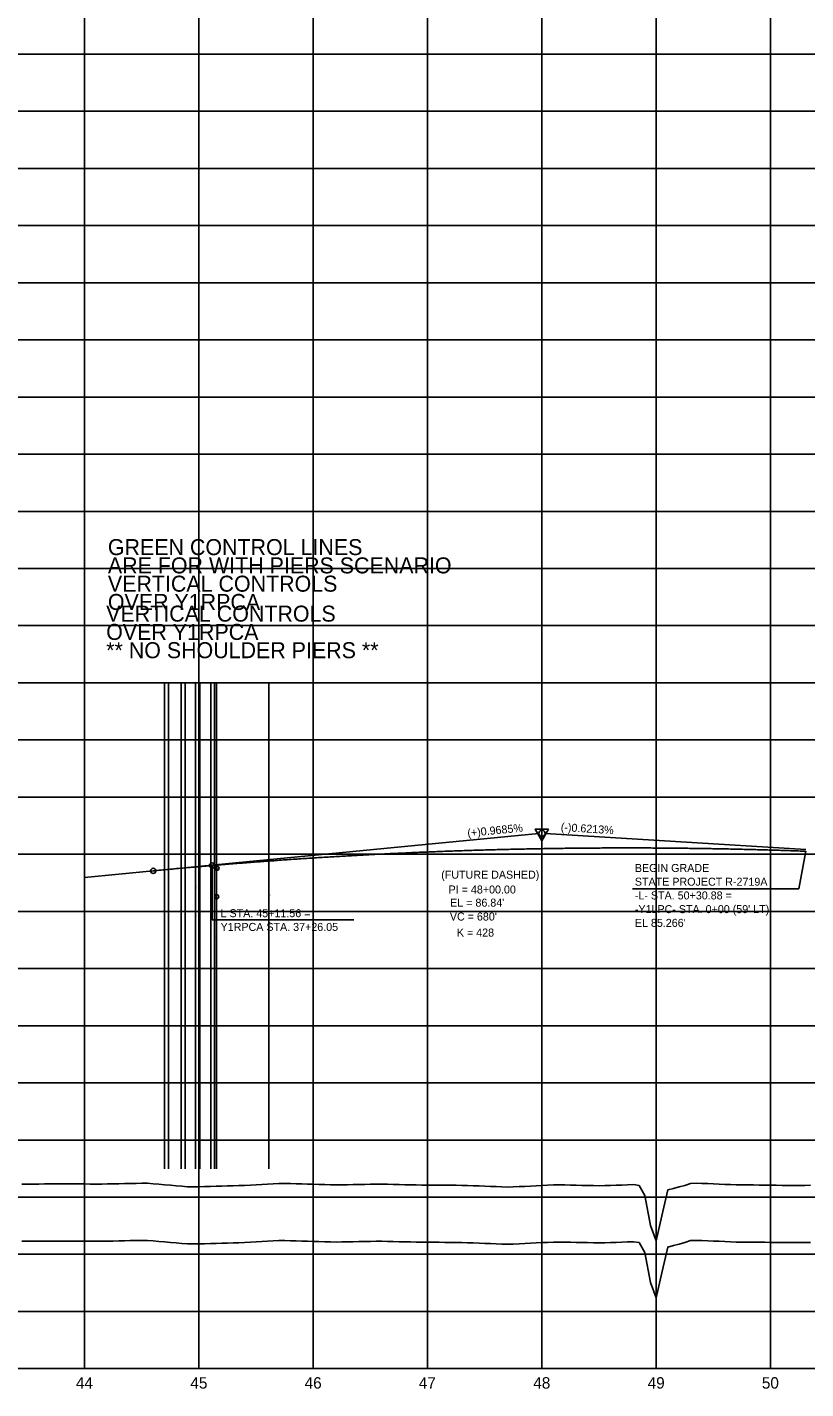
# Model space of a CAD drawing. Extents: x 2345490 to 2436403, y 465165 to 573888.
# Drawn here: x 2384671 to 2385352, y 564259 to 565450 of the extents above; entities that cross this region are included whole.
import ezdxf

# ---------------------------------------------------------------- set-up
doc = ezdxf.new("R2010")
doc.units = 0
for name, color, linetype in [('Old_Level_1', 7, 'Continuous'), ('Old_Level_2', 7, 'Continuous'), ('Old_Level_3', 7, 'Continuous'), ('Old_Level_57', 7, 'Continuous'), ('Old_Level_60', 7, 'Continuous'), ('Old_Level_62', 7, 'Continuous'), ('Old_Level_63', 7, 'Continuous')]:
    doc.layers.add(name, color=color, linetype=linetype)

msp = doc.modelspace()

# ---------------------------------------------------------------- linework, layer by layer
at = {"layer": 'Old_Level_1'}
for points in [[(2384666.5425, 564387.99375), (2384671.5425, 564388.00975), (2384676.5425, 564388.02575), (2384681.5425, 564388.04175), (2384686.5425, 564388.05775), (2384691.5425, 564388.0735), (2384696.5425, 564388.1295), (2384701.5425, 564388.149), (2384706.5425, 564388.12625), (2384711.5425, 564388.10325), (2384716.5425, 564388.0805), (2384721.5425, 564388.0575), (2384726.5425, 564388.03475), (2384731.5425, 564388.01175), (2384736.5425, 564388.001), (2384741.5425, 564388.0535), (2384746.5425, 564388.1665), (2384751.5425, 564388.2795), (2384756.5425, 564388.39275), (2384761.5425, 564388.50575), (2384766.5425, 564388.61875), (2384771.5425, 564388.73175), (2384776.5425, 564388.631), (2384781.5425, 564388.33475), (2384786.5425, 564387.883), (2384791.5425, 564387.43125), (2384796.5425, 564386.9795), (2384801.5425, 564386.52775), (2384806.5425, 564386.076), (2384811.5425, 564385.62425), (2384816.5425, 564385.555), (2384821.5425, 564385.63175), (2384826.5425, 564385.76925), (2384831.5425, 564385.907), (2384836.5425, 564386.04475), (2384841.5425, 564386.1825), (2384846.5425, 564386.32), (2384851.5425, 564386.45775), (2384856.5425, 564386.596), (2384861.5425, 564386.796), (2384866.5425, 564387.07975), (2384871.5425, 564387.36325)], [(2384871.5425, 564387.36325), (2384876.5425, 564387.647), (2384881.5425, 564387.9305), (2384886.5425, 564388.21425), (2384891.5425, 564388.49775), (2384896.5425, 564388.46975), (2384901.5425, 564388.348), (2384906.5425, 564388.203), (2384911.5425, 564388.05775), (2384916.5425, 564387.9125), (2384921.5425, 564387.7675), (2384926.5425, 564387.62225), (2384931.5425, 564387.477), (2384936.5425, 564387.3185), (2384941.5425, 564387.25825), (2384946.5425, 564387.35425), (2384951.5425, 564387.45025), (2384956.5425, 564387.54625), (2384961.5425, 564387.6425), (2384966.5425, 564387.7385), (2384971.5425, 564387.8345), (2384976.5425, 564387.91125), (2384981.5425, 564387.91125), (2384986.5425, 564387.79), (2384991.5425, 564387.66875), (2384996.5425, 564387.5475), (2385001.5425, 564387.42625), (2385006.5425, 564387.30475), (2385011.5425, 564387.1835), (2385016.5425, 564387.134), (2385021.5425, 564387.09925), (2385026.5425, 564387.05925), (2385031.5425, 564387.01925), (2385036.5425, 564386.97925), (2385041.5425, 564386.93925), (2385046.5425, 564386.89925), (2385051.5425, 564386.85925), (2385056.5425, 564386.696), (2385061.5425, 564386.50225), (2385066.5425, 564386.3085), (2385071.5425, 564386.11475), (2385076.5425, 564385.921), (2385081.5425, 564385.72725), (2385086.5425, 564385.5335), (2385091.5425, 564385.33975), (2385096.5425, 564385.50225), (2385101.5425, 564385.7525), (2385106.5425, 564386.00275), (2385111.5425, 564386.253), (2385116.5425, 564386.5035), (2385121.5425, 564386.75375), (2385126.5425, 564387.004), (2385131.5425, 564387.25425), (2385136.5425, 564387.252), (2385141.5425, 564387.17575), (2385146.5425, 564387.07075), (2385151.5425, 564386.966), (2385156.5425, 564386.861), (2385161.5425, 564386.75625), (2385166.5425, 564386.65125), (2385171.5425, 564386.5465), (2385176.5425, 564386.6615), (2385181.5425, 564386.83075), (2385186.5425, 564387), (2385191.5425, 564387.16925), (2385196.5425, 564387.33875), (2385201.5425, 564387.508), (2385206.5425, 564386.848), (2385211.5425, 564377.9725), (2385216.5425, 564351.781), (2385221.5425, 564338.41675), (2385226.5425, 564360.271), (2385231.5425, 564382.79775), (2385236.5425, 564384.12175), (2385241.5425, 564385.45), (2385246.5425, 564386.7805), (2385251.5425, 564388.518), (2385256.5425, 564388.74975), (2385261.5425, 564388.5585), (2385266.5425, 564388.34875), (2385271.5425, 564388.13875), (2385276.5425, 564387.92875), (2385281.5425, 564387.71875), (2385286.5425, 564387.50875), (2385291.5425, 564387.29875), (2385296.5425, 564387.2705), (2385301.5425, 564387.26875), (2385306.5425, 564387.1965), (2385311.5425, 564387.12425), (2385316.5425, 564387.052), (2385321.5425, 564386.98), (2385326.5425, 564386.90775), (2385331.5425, 564386.8355), (2385336.5425, 564386.78225), (2385341.5425, 564386.75275), (2385346.5425, 564386.809), (2385351.5425, 564386.86525), (2385356.5425, 564386.9215)]]:
    msp.add_lwpolyline(points, dxfattribs=at)
at = {"layer": 'Old_Level_2'}
for p, q in [((2384781.5425, 564712.00625), (2385118.8055, 564744.66875)), ((2385352.25775, 564730.5995), (2385124.28725, 564744.76325)), ((2384721.5425, 564706.1955), (2384781.5425, 564712.00625)), ((2385200.893, 564696.2675), (2385346.21025, 564696.2675))]:
    msp.add_line(p, q, dxfattribs=at)
msp.add_lwpolyline([(2385127.35225, 564748.4535), (2385115.60975, 564748.439), (2385121.49325, 564738.32075)], close=True, dxfattribs=at)
for centre, radius in [((2385121.5425, 564744.934), 2.75), ((2384833.1025, 564716.6875), 2.25), ((2384781.5425, 564712.00625), 2.25)]:
    msp.add_circle(centre, radius, dxfattribs=at)
msp.add_spline([(2384781.5425, 564712.00625), (2384795.1425, 564713.30175), (2384808.7425, 564714.554), (2384822.3425, 564715.763), (2384835.9425, 564716.92875), (2384849.5425, 564718.05125), (2384863.1425, 564719.1305), (2384876.7425, 564720.1665), (2384890.3425, 564721.15925), (2384903.9425, 564722.10875), (2384917.5425, 564723.01525), (2384931.1425, 564723.87825), (2384944.7425, 564724.698), (2384958.3425, 564725.47475), (2384971.9425, 564726.208), (2384985.5425, 564726.898), (2384999.1425, 564727.545), (2385012.7425, 564728.1485), (2385026.3425, 564728.709), (2385039.9425, 564729.22625), (2385053.5425, 564729.7), (2385067.1425, 564730.13075), (2385080.7425, 564730.518), (2385094.3425, 564730.86225), (2385107.9425, 564731.16325), (2385121.5425, 564731.421), (2385135.1425, 564731.63525), (2385148.7425, 564731.8065), (2385162.3425, 564731.9345), (2385175.9425, 564732.01925), (2385189.5425, 564732.06075), (2385203.1425, 564732.059), (2385216.7425, 564732.014), (2385230.3425, 564731.92575), (2385243.9425, 564731.79425), (2385257.5425, 564731.6195), (2385271.1425, 564731.4015), (2385284.7425, 564731.14025), (2385298.3425, 564730.83575), (2385311.9425, 564730.48825), (2385325.5425, 564730.09725), (2385339.1425, 564729.663), (2385352.19225, 564729.206)], degree=3, dxfattribs=at)
at = {"layer": 'Old_Level_3'}
for p, q in [((2385352.4225, 564729.198), (2385346.21025, 564696.2675)), ((2384833.1025, 564669.14825), (2384833.1025, 564716.6875)), ((2384833.1025, 564669.14825), (2384956.8955, 564669.14825))]:
    msp.add_line(p, q, dxfattribs=at)
at = {"layer": 'Old_Level_57'}
for p, q in [((2384721.54225, 564276.534), (2384721.54225, 566615.2835)), ((2384821.54225, 564276.534), (2384821.54225, 566615.2835)), ((2384921.5425, 564276.534), (2384921.5425, 566615.2835)), ((2385021.54225, 564276.534), (2385021.54225, 566615.2835)), ((2385121.54225, 564276.534), (2385121.54225, 566615.2835)), ((2385221.54225, 564276.534), (2385221.54225, 566615.2835)), ((2385321.5425, 564276.534), (2385321.5425, 566615.2835)), ((2381271.5425, 565426.534), (2410861.12275, 565426.534)), ((2381271.5425, 565376.534), (2410861.12275, 565376.534)), ((2381271.5425, 565326.534), (2410861.12275, 565326.534)), ((2381271.5425, 565276.534), (2410861.12275, 565276.534)), ((2381271.5425, 565226.534), (2410861.12275, 565226.534)), ((2381271.5425, 565176.534), (2410861.12275, 565176.534)), ((2381271.5425, 565126.534), (2410861.12275, 565126.534)), ((2381271.5425, 565076.534), (2410861.12275, 565076.534)), ((2381271.5425, 565026.534), (2410861.12275, 565026.534)), ((2381271.5425, 564976.534), (2410861.12275, 564976.534)), ((2381271.5425, 564926.534), (2410861.12275, 564926.534)), ((2381271.5425, 564876.534), (2410861.12275, 564876.534)), ((2381271.5425, 564826.534), (2410861.12275, 564826.534)), ((2381271.54275, 564776.534), (2410861.123, 564776.534)), ((2381271.5425, 564726.534), (2410861.12275, 564726.534)), ((2381271.54275, 564676.534), (2410861.123, 564676.534)), ((2381271.5425, 564626.534), (2410861.12275, 564626.534)), ((2381271.54275, 564576.534), (2410861.123, 564576.534)), ((2381271.5425, 564526.534), (2410861.12275, 564526.534)), ((2381271.54275, 564476.534), (2410861.123, 564476.534)), ((2381271.5425, 564426.534), (2410861.12275, 564426.534)), ((2381271.54275, 564376.534), (2410861.123, 564376.534)), ((2381271.5425, 564326.534), (2410861.12275, 564326.534)), ((2381271.54275, 564276.534), (2410861.123, 564276.534))]:
    msp.add_line(p, q, dxfattribs=at)
at = {"layer": 'Old_Level_60'}
for p, q in [((2384791.5225, 564682.944), (2384791.5225, 564877.041)), ((2384794.9525, 564680.684), (2384794.9525, 564877.041)), ((2384806.1225, 564673.834), (2384806.1225, 564877.041)), ((2384809.4725, 564672.114), (2384809.4725, 564877.041)), ((2384818.6825, 564674.514), (2384818.6825, 564877.041)), ((2384822.4225, 564678.084), (2384822.4225, 564877.041)), ((2384831.8625, 564686.984), (2384831.8625, 564877.041)), ((2384835.2025, 564657.624), (2384835.2025, 564877.041)), ((2384836.8325, 564691.624), (2384836.8325, 564877.041)), ((2384882.5625, 564668.344), (2384882.5625, 564877.041)), ((2384831.8625, 564681.984), (2384831.8625, 564451.45825)), ((2384836.8325, 564686.624), (2384836.8325, 564451.45825)), ((2384791.5225, 564677.944), (2384791.5225, 564451.45825)), ((2384794.9525, 564675.684), (2384794.9525, 564451.45825)), ((2384806.1225, 564668.834), (2384806.1225, 564451.45825)), ((2384818.6825, 564669.514), (2384818.6825, 564451.45825)), ((2384822.4225, 564673.084), (2384822.4225, 564451.45825)), ((2384809.4725, 564667.114), (2384809.4725, 564451.45825)), ((2384882.5625, 564663.344), (2384882.5625, 564451.45825)), ((2384835.2025, 564652.624), (2384835.2025, 564451.45825))]:
    msp.add_line(p, q, dxfattribs=at)
msp.add_circle((2384837.05425, 564689.321), 1.81196, dxfattribs=at)
at = {"layer": 'Old_Level_63'}
for p, q in [((2384791.5225, 564708.694), (2384791.5225, 564760.1775)), ((2384794.9525, 564706.184), (2384794.9525, 564760.1775)), ((2384806.1225, 564699.334), (2384806.1225, 564760.1775)), ((2384809.4725, 564697.614), (2384809.4725, 564760.1775)), ((2384818.6825, 564700.014), (2384818.6825, 564760.1775)), ((2384822.4225, 564703.584), (2384822.4225, 564760.1775)), ((2384831.8625, 564712.484), (2384831.8625, 564760.1775)), ((2384835.2025, 564683.374), (2384835.2025, 564760.1775)), ((2384836.8325, 564717.124), (2384836.8325, 564760.1775)), ((2384882.5625, 564693.844), (2384882.5625, 564760.1775)), ((2384791.5225, 564703.694), (2384791.5225, 564617.51525)), ((2384831.8625, 564707.484), (2384831.8625, 564617.51525)), ((2384836.8325, 564712.124), (2384836.8325, 564617.51525)), ((2384794.9525, 564701.184), (2384794.9525, 564617.51525)), ((2384806.1225, 564694.334), (2384806.1225, 564617.51525)), ((2384809.4725, 564692.614), (2384809.4725, 564617.51525)), ((2384818.6825, 564695.014), (2384818.6825, 564617.51525)), ((2384822.4225, 564698.584), (2384822.4225, 564617.51525)), ((2384882.5625, 564688.844), (2384882.5625, 564617.51525)), ((2384835.2025, 564678.374), (2384835.2025, 564617.51525)), ((2381321.5425, 564276.534), (2406689.937, 564276.534))]:
    msp.add_line(p, q, dxfattribs=at)
for points in [[(2384666.5425, 564437.9935), (2384671.5425, 564438.0095), (2384676.5425, 564438.0255), (2384681.5425, 564438.0415), (2384686.5425, 564438.0575), (2384691.5425, 564438.07325), (2384696.5425, 564438.12925), (2384701.5425, 564438.14875), (2384706.5425, 564438.126), (2384711.5425, 564438.103), (2384716.5425, 564438.08025), (2384721.5425, 564438.05725), (2384726.5425, 564438.0345), (2384731.5425, 564438.0115), (2384736.5425, 564438.00075), (2384741.5425, 564438.05325), (2384746.5425, 564438.16625), (2384751.5425, 564438.27925), (2384756.5425, 564438.3925), (2384761.5425, 564438.5055), (2384766.5425, 564438.6185), (2384771.5425, 564438.7315), (2384776.5425, 564438.63075), (2384781.5425, 564438.3345), (2384786.5425, 564437.88275), (2384791.5425, 564437.431), (2384796.5425, 564436.97925), (2384801.5425, 564436.5275), (2384806.5425, 564436.07575), (2384811.5425, 564435.624), (2384816.5425, 564435.55475), (2384821.5425, 564435.6315), (2384826.5425, 564435.769), (2384831.5425, 564435.90675), (2384836.5425, 564436.0445), (2384841.5425, 564436.18225), (2384846.5425, 564436.31975), (2384851.5425, 564436.4575), (2384856.5425, 564436.59575), (2384861.5425, 564436.79575), (2384866.5425, 564437.0795), (2384871.5425, 564437.363)], [(2384871.5425, 564437.363), (2384876.5425, 564437.64675), (2384881.5425, 564437.93025), (2384886.5425, 564438.214), (2384891.5425, 564438.4975), (2384896.5425, 564438.4695), (2384901.5425, 564438.34775), (2384906.5425, 564438.20275), (2384911.5425, 564438.0575), (2384916.5425, 564437.91225), (2384921.5425, 564437.76725), (2384926.5425, 564437.622), (2384931.5425, 564437.47675), (2384936.5425, 564437.31825), (2384941.5425, 564437.258), (2384946.5425, 564437.354), (2384951.5425, 564437.45), (2384956.5425, 564437.546), (2384961.5425, 564437.64225), (2384966.5425, 564437.73825), (2384971.5425, 564437.83425), (2384976.5425, 564437.911), (2384981.5425, 564437.911), (2384986.5425, 564437.78975), (2384991.5425, 564437.6685), (2384996.5425, 564437.54725), (2385001.5425, 564437.426), (2385006.5425, 564437.3045), (2385011.5425, 564437.18325), (2385016.5425, 564437.13375), (2385021.5425, 564437.099), (2385026.5425, 564437.059), (2385031.5425, 564437.019), (2385036.5425, 564436.979), (2385041.5425, 564436.939), (2385046.5425, 564436.899), (2385051.5425, 564436.859), (2385056.5425, 564436.69575), (2385061.5425, 564436.502), (2385066.5425, 564436.30825), (2385071.5425, 564436.1145), (2385076.5425, 564435.92075), (2385081.5425, 564435.727), (2385086.5425, 564435.53325), (2385091.5425, 564435.3395), (2385096.5425, 564435.502), (2385101.5425, 564435.75225), (2385106.5425, 564436.0025), (2385111.5425, 564436.25275), (2385116.5425, 564436.50325), (2385121.5425, 564436.7535), (2385126.5425, 564437.00375), (2385131.5425, 564437.254), (2385136.5425, 564437.25175), (2385141.5425, 564437.1755), (2385146.5425, 564437.0705), (2385151.5425, 564436.96575), (2385156.5425, 564436.86075), (2385161.5425, 564436.756), (2385166.5425, 564436.651), (2385171.5425, 564436.54625), (2385176.5425, 564436.66125), (2385181.5425, 564436.8305), (2385186.5425, 564436.99975), (2385191.5425, 564437.169), (2385196.5425, 564437.3385), (2385201.5425, 564437.50775), (2385206.5425, 564436.84775), (2385211.5425, 564427.97225), (2385216.5425, 564401.78075), (2385221.5425, 564388.4165), (2385226.5425, 564410.27075), (2385231.5425, 564432.7975), (2385236.5425, 564434.1215), (2385241.5425, 564435.44975), (2385246.5425, 564436.78025), (2385251.5425, 564438.51775), (2385256.5425, 564438.7495), (2385261.5425, 564438.55825), (2385266.5425, 564438.3485), (2385271.5425, 564438.1385), (2385276.5425, 564437.9285), (2385281.5425, 564437.7185), (2385286.5425, 564437.5085), (2385291.5425, 564437.2985), (2385296.5425, 564437.27025), (2385301.5425, 564437.2685), (2385306.5425, 564437.19625), (2385311.5425, 564437.124), (2385316.5425, 564437.05175), (2385321.5425, 564436.97975), (2385326.5425, 564436.9075), (2385331.5425, 564436.83525), (2385336.5425, 564436.782), (2385341.5425, 564436.7525), (2385346.5425, 564436.80875), (2385351.5425, 564436.865), (2385356.5425, 564436.92125)]]:
    msp.add_lwpolyline(points, dxfattribs=at)
msp.add_circle((2384837.29783, 564714.28998), 1.81196, dxfattribs=at)

# ---------------------------------------------------------------- texts
at = {"layer": 'Old_Level_2'}
for s, rotation, p in [('(+)0.9685%', 5.531625, (2385056.702, 564741.66825)), ('(-)0.6213%', 356.44477222, (2385137.89175, 564746.92375))]:
    msp.add_text(s, height=7.000001, rotation=rotation, dxfattribs=at).set_placement(p)
for s, height, p in [('BEGIN GRADE', 7.0000005, (2385202.84275, 564711.013)), ('(FUTURE DASHED)', 7.0000005, (2385033.46225, 564705.18875)), ('STATE PROJECT R-2719A', 7.0000005, (2385202.84275, 564699.01275)), ('PI = 48+00.00', 7.0000005, (2385039.93325, 564692.2015)), ('-L- STA. 50+30.88 =', 7.0000005, (2385202.84275, 564687.01275)), ("EL = 86.84'", 7.0000005, (2385041.27425, 564680.7065)), ("-Y1LPC- STA. 0+00 (59' LT)", 7.0000005, (2385202.84275, 564675.01275)), ("VC = 680'", 7.000001, (2385041.02225, 564668.55)), ("EL 85.266'", 7.000001, (2385202.84275, 564663.01275)), ('K = 428', 7.000001, (2385047.16725, 564654.54025))]:
    msp.add_text(s, height=height, dxfattribs=at).set_placement(p)
at = {"layer": 'Old_Level_3'}
for s, p in [('L STA. 45+11.56 = ', (2384840.489, 564671.46125)), ('Y1RPCA STA. 37+26.05', (2384840.489, 564659.461))]:
    msp.add_text(s, height=7.0000005, dxfattribs=at).set_placement(p)
at = {"layer": 'Old_Level_60'}
for s, height, p in [('GREEN CONTROL LINES ', 14.000001, (2384741.90425, 564988.26725)), ('ARE FOR WITH PIERS SCENARIO', 14.000001, (2384741.90425, 564972.26725)), ('VERTICAL CONTROLS', 14.000001, (2384741.90425, 564956.26725)), ('OVER Y1RPCA', 14.000001, (2384741.90425, 564940.26725)), ('2', 1.75, (2384790.78975, 564679.72425)), ('8', 1.75, (2384831.54175, 564683.68725)), ('9', 1.75, (2384836.447, 564688.59375)), ('3', 1.75, (2384794.3745, 564677.27075)), ('4', 1.75, (2384805.317, 564670.8545)), ('5', 1.75, (2384808.90175, 564668.77875)), ('6', 1.75, (2384818.52375, 564671.232)), ('7', 1.75, (2384822.297, 564674.8175)), ('1', 1.75, (2384834.813, 564653.92325)), ('10', 1.750001, (2384881.72725, 564665.193))]:
    msp.add_text(s, height=height, dxfattribs=at).set_placement(p)
at = {"layer": 'Old_Level_62'}
for s, p in [('44', (2384713.994, 564259.034)), ('45', (2384814.0865, 564259.034)), ('46', (2384914.0275, 564259.034)), ('47', (2385013.885, 564259.034)), ('48', (2385114.01075, 564259.034)), ('49', (2385214.053, 564259.034)), ('50', (2385313.929, 564259.034))]:
    msp.add_text(s, height=10.000001, dxfattribs=at).set_placement(p)
at = {"layer": 'Old_Level_63'}
for s, height, p in [('VERTICAL CONTROLS', 14.000001, (2384740.42375, 564930.06325)), ('OVER Y1RPCA', 14.000001, (2384740.42375, 564914.06325)), ('** NO SHOULDER PIERS **', 14.000001, (2384740.42375, 564898.06325)), ('2', 1.75, (2384790.557, 564705.2785)), ('3', 1.75, (2384794.03625, 564702.38525)), ('8', 1.75, (2384831.058, 564709.09275)), ('9', 1.75, (2384836.982, 564713.12575)), ('4', 1.75, (2384805.1245, 564695.96875)), ('5', 1.75, (2384808.70925, 564694.4755)), ('6', 1.75, (2384818.47675, 564696.783)), ('7', 1.75, (2384821.95875, 564700.223)), ('10', 1.750001, (2384881.80725, 564690.125)), ('1', 1.75, (2384834.79975, 564680.09425))]:
    msp.add_text(s, height=height, dxfattribs=at).set_placement(p)

doc.saveas('drawing.dxf')
